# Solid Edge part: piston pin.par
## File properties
Author: Deepak Maini
Template: Normal.par
Last saved by: Robert a Rhodes jr
Revision: 2
Application: Solid Edge
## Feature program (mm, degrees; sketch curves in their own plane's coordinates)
sketch for "unnamed Protrusion 1" #1 plane through (0, 0, 0) normal (0, 0, 1) x-axis (1, 0, 0)
  circle centre (0, 0) radius 5.5
sketch for "unnamed Protrusion 1" #2 plane through (0, 0, 0) normal (0, 0, 1) x-axis (1, 0, 0)
  circle centre (0, 0) radius 11
extrude "unnamed Protrusion 1" add finite 80 along -normal
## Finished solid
Body 1: solid body, 4 faces, 4 edges, 0 vertices.
  Faces by surface: cylinder 2, plane 2
  Edges by curve: circle 4
Bounding box of the edges (mm): 22.000 x 22.000 x 80.000, from (-11, -11, -80) to (11, 11, 0).
Cylindrical faces by radius (mm): R5.5 x1, R11 x1
Planar faces by outward normal: +z 1, -z 1
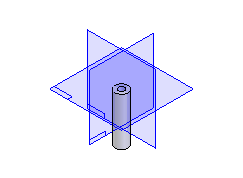
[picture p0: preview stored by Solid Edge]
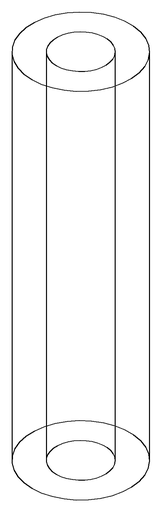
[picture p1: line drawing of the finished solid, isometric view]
